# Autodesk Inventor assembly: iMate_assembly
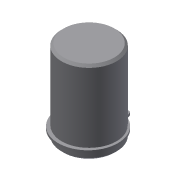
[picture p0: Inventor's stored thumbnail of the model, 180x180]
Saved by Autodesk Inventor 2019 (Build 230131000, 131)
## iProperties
Created: 2016-08
Part Number: iMate_assembly
Document SubType Name: Assembly
Designer: Sandeep
Author: Sandeep
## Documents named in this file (3)
- E:\_Deepak\Inventor\Projects\Autodesk Inventor_2019_Project\Resources\Inventor_2018_tut\c17_Inv_2019_tut\c17_Inv_tut_2019\c17_tut02\iMate_assembly.iam
- E:\_Deepak\Inventor\Projects\Autodesk Inventor_2019_Project\Resources\Inventor_2018_tut\c17_Inv_2019_tut\c17_Inv_tut_2019\c17_tut02\Shaft.ipt
- E:\_Deepak\Inventor\Projects\Autodesk Inventor_2019_Project\Resources\Inventor_2018_tut\c17_Inv_2019_tut\c17_Inv_tut_2019\c17_tut02\circlip.ipt
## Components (2 placed, 2 different names)
1. Shaft:1
2. circlip:1
